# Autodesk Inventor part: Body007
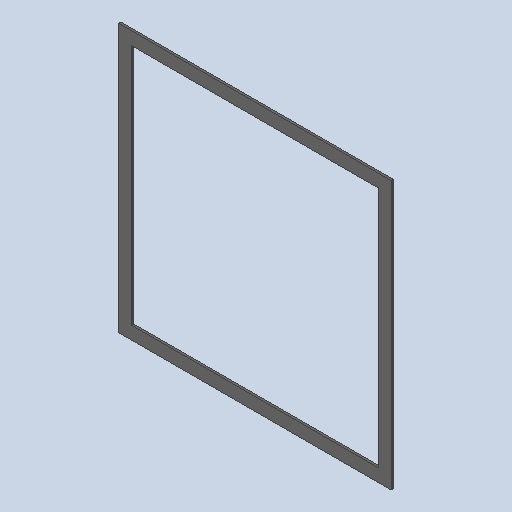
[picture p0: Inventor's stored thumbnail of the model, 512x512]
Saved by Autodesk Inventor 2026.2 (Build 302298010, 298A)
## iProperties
Created: 2026-10
Part Number: Body007
Material: Générique
Document SubType Name: Modeling
Designer: mel
Density: 1 g/cm^3
Appearance: Par défaut
Author: mel
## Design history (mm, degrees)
feature "Base1"
node "Solide1"
